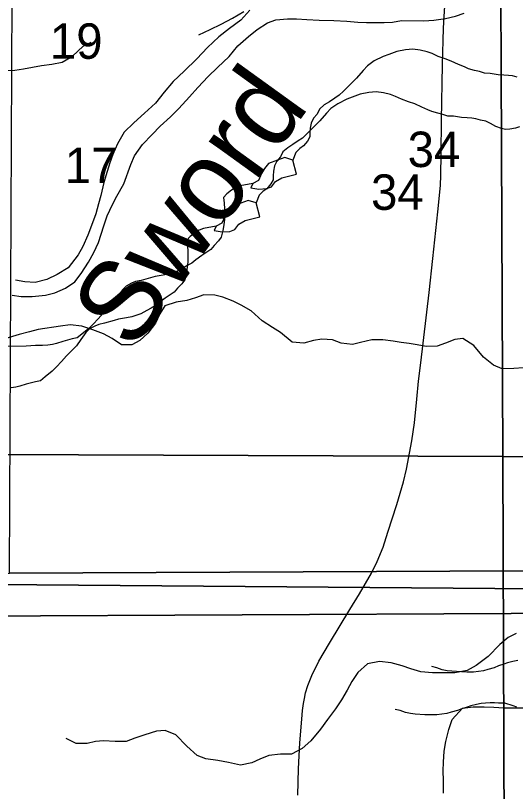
# Model space of a CAD drawing. Extents: x -21.1 to 50.3, y -4.9 to 22.1.
# Drawn here: x 5.889 to 6.48, y 18.75 to 19.666 of the extents above; entities that cross this region are included whole.
import ezdxf

# ---------------------------------------------------------------- set-up
doc = ezdxf.new("R2010")
doc.units = 0
for name, color, linetype in [('GM_X_Minor_Lake', 7, 'Continuous'), ('GM_X_Minor_River', 7, 'Continuous'), ('GM_X_Minor_River_Text', 7, 'Continuous'), ('GM_X_Section', 7, 'Continuous'), ('GM_X_Section_Text', 7, 'Continuous'), ('GM_X_State_Route', 7, 'Continuous')]:
    doc.layers.add(name, color=color, linetype=linetype)

msp = doc.modelspace()

# ---------------------------------------------------------------- linework, layer by layer
at = {"layer": 'GM_X_Minor_Lake'}
for points in [[(6.21674, 19.49534), (6.20723, 19.49828), (6.19854, 19.49515), (6.18797, 19.49124), (6.1831, 19.4855), (6.17975, 19.47939), (6.17605, 19.47138), (6.16926, 19.46789), (6.16705, 19.46256), (6.17654, 19.46114), (6.18564, 19.46162), (6.1913, 19.46395), (6.19617, 19.47008), (6.2037, 19.47433), (6.21165, 19.47632), (6.2211, 19.47869)], [(6.2211, 19.47869), (6.21674, 19.49534)], [(6.17345, 19.44483), (6.16394, 19.44776), (6.15525, 19.44463), (6.14468, 19.44072), (6.13981, 19.43498), (6.13646, 19.42887), (6.13276, 19.42086), (6.12598, 19.41738), (6.12376, 19.41204), (6.13326, 19.41062), (6.14235, 19.4111), (6.14802, 19.41344), (6.15288, 19.41956), (6.16042, 19.42382), (6.16836, 19.4258), (6.17781, 19.42818)], [(6.17781, 19.42818), (6.17345, 19.44483)]]:
    msp.add_lwpolyline(points, dxfattribs=at)
at = {"layer": 'GM_X_Minor_River'}
for points in [[(5.8849, 19.33589), (5.89589, 19.33426), (5.9088, 19.33413), (5.92438, 19.33587), (5.93541, 19.33841), (5.948, 19.34398), (5.95909, 19.35147), (5.9664, 19.36127), (5.97527, 19.37486), (5.98146, 19.38619), (5.9869, 19.39791), (5.99003, 19.40776), (5.99355, 19.4176), (5.99747, 19.42933), (6.00368, 19.44294), (6.00872, 19.45277), (6.01684, 19.4675), (6.02543, 19.49021), (6.02971, 19.50042), (6.03895, 19.51362), (6.05047, 19.52566), (6.06006, 19.53544), (6.07232, 19.54633), (6.08191, 19.55649), (6.09458, 19.57004), (6.10456, 19.58095), (6.11647, 19.59412), (6.12758, 19.60465), (6.14138, 19.6178), (6.15176, 19.63023), (6.16441, 19.6415), (6.17436, 19.64976), (6.18659, 19.65761), (6.19649, 19.66093), (6.21055, 19.66231), (6.22118, 19.6622), (6.23332, 19.66132), (6.24774, 19.66079), (6.2652, 19.66023), (6.28037, 19.65932), (6.29365, 19.65843), (6.30389, 19.65794), (6.32477, 19.65773), (6.33427, 19.65839), (6.34491, 19.66018), (6.37148, 19.65991), (6.38326, 19.66056), (6.39695, 19.6627), (6.40874, 19.66524), (6.41903, 19.66893)], [(6.16586, 19.67226), (6.15511, 19.66059), (6.14173, 19.65085), (6.1291, 19.6411), (6.11568, 19.62832), (6.1034, 19.61515), (6.08844, 19.60049), (6.07541, 19.58808), (6.06465, 19.57566), (6.05426, 19.56247), (6.04124, 19.55082), (6.02897, 19.53955), (6.01747, 19.52827), (6.00936, 19.51468), (6.00391, 19.50182), (6.00039, 19.49198), (5.99725, 19.48176), (5.99332, 19.46888), (5.98975, 19.45372), (5.98699, 19.44387), (5.98383, 19.43175), (5.97992, 19.42115), (5.97446, 19.40677), (5.96863, 19.39316), (5.96321, 19.38334), (5.95129, 19.36826), (5.9383, 19.36004), (5.92609, 19.35446), (5.91239, 19.3508), (5.89987, 19.35169), (5.88888, 19.3537)], [(6.10577, 19.64349), (6.11904, 19.64956), (6.13193, 19.65601), (6.1452, 19.66284), (6.15886, 19.67081)], [(5.72814, 19.54864), (5.74103, 19.5494), (5.7543, 19.55129), (5.7691, 19.56381), (5.78161, 19.57595), (5.7945, 19.58467), (5.80777, 19.58505), (5.81952, 19.58051), (5.83128, 19.58126), (5.84265, 19.59226), (5.85593, 19.59833), (5.86616, 19.59947), (5.87867, 19.60099), (5.88815, 19.60175), (5.89839, 19.60327), (5.909, 19.60517), (5.91962, 19.60706), (5.93175, 19.60858), (5.94426, 19.61086), (5.9564, 19.61807), (5.96891, 19.62983), (5.97839, 19.63476)], [(6.4817, 19.59322), (6.47636, 19.59471), (6.47141, 19.59544), (6.46608, 19.59579), (6.45922, 19.59613), (6.4497, 19.5976), (6.44322, 19.59795), (6.43712, 19.59981), (6.4314, 19.6013), (6.42416, 19.60316), (6.41958, 19.60541), (6.41233, 19.60841), (6.40394, 19.61216), (6.39669, 19.61478), (6.3883, 19.61778), (6.38143, 19.62116), (6.37533, 19.6234), (6.36694, 19.62526), (6.35856, 19.62635), (6.34981, 19.62554), (6.33954, 19.62358), (6.33004, 19.62011), (6.32359, 19.6178), (6.31296, 19.61242), (6.305, 19.60668), (6.2997, 19.60133), (6.29176, 19.59217), (6.27661, 19.57689), (6.27131, 19.57192), (6.26638, 19.56847), (6.25994, 19.56426), (6.25387, 19.56043), (6.24818, 19.55546), (6.24555, 19.54975), (6.24101, 19.54478), (6.23838, 19.53907), (6.23727, 19.53298), (6.23692, 19.52728), (6.23657, 19.52272), (6.23393, 19.51777), (6.2294, 19.51205), (6.22484, 19.50898), (6.22037, 19.50433), (6.21671, 19.49535)], [(6.48451, 19.5346), (6.47957, 19.53305), (6.47311, 19.53188), (6.46778, 19.53147), (6.46321, 19.53258), (6.45634, 19.53521), (6.45023, 19.53859), (6.44451, 19.54122), (6.43841, 19.5427), (6.43307, 19.54419), (6.42812, 19.54493), (6.42279, 19.54528), (6.41593, 19.54562), (6.40641, 19.54708), (6.39994, 19.54743), (6.39383, 19.5493), (6.38812, 19.55078), (6.38087, 19.55264), (6.37629, 19.5549), (6.36904, 19.5579), (6.36065, 19.56165), (6.3534, 19.56427), (6.34501, 19.56726), (6.33814, 19.57064), (6.33204, 19.57289), (6.32365, 19.57474), (6.31527, 19.57583), (6.30652, 19.57502), (6.29625, 19.57307), (6.28676, 19.5696), (6.2803, 19.56728), (6.26967, 19.5619), (6.26171, 19.55616), (6.25641, 19.55081), (6.24847, 19.54165), (6.23332, 19.52637), (6.22802, 19.5214), (6.2231, 19.51796), (6.21665, 19.51375), (6.21058, 19.50991), (6.20489, 19.50494), (6.20226, 19.49923), (6.19772, 19.49427), (6.19509, 19.48855), (6.19398, 19.48247), (6.19363, 19.47677), (6.19328, 19.47221), (6.19064, 19.46725), (6.18611, 19.46153), (6.18155, 19.45847), (6.17708, 19.45381), (6.17342, 19.44484)], [(6.16926, 19.46789), (6.15453, 19.46495), (6.14935, 19.46298), (6.14404, 19.45991), (6.13873, 19.4557), (6.13457, 19.45112), (6.13537, 19.44467), (6.13579, 19.43783), (6.13586, 19.42568), (6.13513, 19.41883), (6.13403, 19.41237), (6.13217, 19.40438), (6.12877, 19.3998), (6.12385, 19.39446), (6.11969, 19.38988), (6.10907, 19.3826), (6.10225, 19.37762), (6.09732, 19.3738)], [(6.12598, 19.41738), (6.11124, 19.41444), (6.10606, 19.41246), (6.10075, 19.4094), (6.09544, 19.40519), (6.09128, 19.4006), (6.09208, 19.39415), (6.0925, 19.38731), (6.09257, 19.37516), (6.09185, 19.36832), (6.09074, 19.36185), (6.08888, 19.35386), (6.08548, 19.34929), (6.08056, 19.34394), (6.0764, 19.33936), (6.06578, 19.33208), (6.05896, 19.32711), (6.05403, 19.32328)], [(6.09732, 19.3738), (6.09277, 19.37111), (6.08745, 19.36804), (6.08024, 19.3642), (6.07568, 19.36266), (6.0696, 19.36073), (6.06352, 19.35955), (6.05401, 19.35798), (6.04869, 19.35643), (6.03729, 19.35333), (6.03083, 19.35178), (6.02589, 19.34985), (6.01982, 19.3464), (6.01527, 19.34219), (6.00961, 19.3338), (6.00432, 19.32655), (5.99903, 19.32083), (5.99259, 19.31471), (5.98654, 19.30784), (5.98086, 19.30173), (5.97556, 19.29638), (5.96722, 19.28988), (5.96192, 19.28529), (5.95584, 19.28412), (5.94482, 19.28102), (5.9376, 19.2787), (5.93265, 19.27753), (5.92733, 19.27675), (5.92086, 19.27633), (5.91249, 19.27628), (5.90716, 19.27587), (5.90145, 19.27546), (5.87823, 19.27534)], [(6.20225, 19.29154), (6.19278, 19.29761), (6.18027, 19.30557), (6.16739, 19.31733), (6.15564, 19.32415), (6.14617, 19.32871), (6.13404, 19.33326), (6.12456, 19.33591), (6.11168, 19.33629), (6.10182, 19.33249), (6.09158, 19.32946), (6.07869, 19.32756), (6.06542, 19.32339), (6.05973, 19.3139), (6.05442, 19.3029), (6.04531, 19.29077), (6.03583, 19.28242), (6.02635, 19.27711), (6.01422, 19.27711), (6.00323, 19.28469), (5.993, 19.29), (5.98049, 19.29493), (5.96722, 19.2991), (5.95358, 19.30062), (5.9422, 19.2991), (5.91566, 19.2953), (5.90543, 19.29265), (5.89329, 19.28923), (5.87775, 19.28468)], [(6.05403, 19.32328), (6.04948, 19.3206), (6.04417, 19.31753), (6.03695, 19.31369), (6.03239, 19.31215), (6.02631, 19.31021), (6.02023, 19.30904), (6.01072, 19.30747), (6.0054, 19.30592), (5.994, 19.30282), (5.98754, 19.30126), (5.9826, 19.29933), (5.97653, 19.29588), (5.97199, 19.29168), (5.96632, 19.28329), (5.96103, 19.27604), (5.95574, 19.27031), (5.9493, 19.2642), (5.94325, 19.25733), (5.93757, 19.25122), (5.93227, 19.24587), (5.92394, 19.23937), (5.91863, 19.23478), (5.91255, 19.23361), (5.90153, 19.2305), (5.89431, 19.22818), (5.88936, 19.22702), (5.88404, 19.22623)], [(6.48919, 19.24986), (6.47782, 19.2491), (6.46417, 19.24872), (6.45394, 19.25326), (6.44182, 19.26274), (6.43045, 19.2764), (6.41757, 19.28474), (6.40809, 19.2836), (6.39709, 19.27905), (6.38724, 19.27564), (6.37435, 19.27525), (6.36373, 19.27715), (6.35426, 19.27867), (6.34478, 19.2798), (6.3353, 19.28132), (6.32318, 19.28321), (6.30991, 19.28321), (6.29664, 19.2798), (6.28716, 19.27752), (6.27389, 19.27904), (6.26366, 19.28321), (6.25077, 19.28396), (6.24092, 19.28207), (6.22954, 19.27903), (6.2159, 19.28017), (6.20225, 19.29154)], [(6.48069, 18.9362), (6.47121, 18.93164), (6.46135, 18.9233), (6.44732, 18.90889), (6.43328, 18.89826), (6.42267, 18.89257), (6.40826, 18.88954), (6.39651, 18.88954), (6.38172, 18.88991), (6.36808, 18.89105), (6.35595, 18.89446), (6.34572, 18.89787), (6.33283, 18.90167), (6.31918, 18.90318), (6.30478, 18.90052), (6.2934, 18.89028), (6.28657, 18.87966), (6.28088, 18.86942), (6.27405, 18.85766), (6.26722, 18.84704), (6.25774, 18.83453), (6.24939, 18.82315), (6.23801, 18.80949), (6.22777, 18.80039), (6.21526, 18.79356), (6.20199, 18.79356), (6.18835, 18.79204), (6.17773, 18.78787), (6.16825, 18.78332), (6.15498, 18.78066), (6.14058, 18.78369), (6.12807, 18.78635), (6.11404, 18.78824), (6.10381, 18.79203), (6.0913, 18.80303), (6.07842, 18.8163), (6.06592, 18.82161), (6.05568, 18.82085), (6.04165, 18.81668), (6.0299, 18.81251), (6.01966, 18.80871), (6.00677, 18.80871), (5.99312, 18.80947), (5.98365, 18.80871), (5.97379, 18.80643), (5.96052, 18.80643), (5.94877, 18.81212)], [(6.4825, 18.90411), (6.4768, 18.90294), (6.47034, 18.90138), (6.46578, 18.89984), (6.4597, 18.8979), (6.45438, 18.8956), (6.44716, 18.89366), (6.44184, 18.89211), (6.43613, 18.89132), (6.43005, 18.89052), (6.42243, 18.89048), (6.41596, 18.89083), (6.40454, 18.89152), (6.39883, 18.89225), (6.39311, 18.89336), (6.38663, 18.8956), (6.38091, 18.89709)], [(6.48149, 18.84927), (6.47692, 18.85076), (6.467, 18.85375), (6.45977, 18.85371), (6.45481, 18.85444), (6.44987, 18.85441), (6.44416, 18.854), (6.43921, 18.85359), (6.43351, 18.85242), (6.42705, 18.85087), (6.42249, 18.84932), (6.41641, 18.84739), (6.41109, 18.84508), (6.40387, 18.84314), (6.39855, 18.84159), (6.39285, 18.8408), (6.38676, 18.84001), (6.37915, 18.83997), (6.37267, 18.84031), (6.36125, 18.84101), (6.35554, 18.84173), (6.34982, 18.84284), (6.34334, 18.84509), (6.33762, 18.84657)], [(6.39473, 18.74763), (6.3945, 18.76245), (6.39424, 18.77385), (6.39473, 18.7841), (6.39562, 18.79738), (6.39726, 18.80876), (6.40082, 18.82278), (6.40512, 18.83451), (6.41702, 18.84807), (6.42956, 18.84946), (6.44285, 18.84971), (6.45424, 18.84921), (6.46599, 18.84833), (6.47586, 18.84823), (6.48953, 18.84847)]]:
    msp.add_lwpolyline(points, dxfattribs=at)
at = {"layer": 'GM_X_Section'}
for points in [[(5.46449, 20.1514), (6.46064, 20.14904), (6.46467, 19.14528), (5.46172, 19.1492)], [(6.46064, 20.14904), (7.44997, 20.14748), (7.45853, 19.14217), (6.46467, 19.14528)], [(5.88662, 20.02845), (6.88082, 20.03211), (6.88772, 19.01332), (6.83581, 19.01172), (5.8818, 19.00728)], [(5.45185, 20.01395), (6.49363, 20.00748), (6.50457, 18.98884), (5.47114, 18.99721)], [(5.84333, 19.97793), (6.83753, 19.9816), (6.84443, 18.96281), (6.79252, 18.9612), (5.83851, 18.95676)], [(5.46172, 19.1492), (6.46467, 19.14528), (6.46827, 18.13471), (5.45742, 18.14589)], [(6.46467, 19.14528), (7.45853, 19.14217), (7.46215, 18.13462), (6.46827, 18.13471)], [(6.83581, 19.01172), (6.83569, 18.01448), (5.81893, 17.99203), (5.82494, 19.00715), (5.8818, 19.00728)], [(6.50457, 18.98884), (6.51666, 17.95921), (5.48815, 17.97251), (5.47114, 18.99721)], [(6.79252, 18.9612), (6.7924, 17.96396), (5.77564, 17.94152), (5.78166, 18.95663), (5.83851, 18.95676)]]:
    msp.add_lwpolyline(points, close=True, dxfattribs=at)
at = {"layer": 'GM_X_State_Route'}
msp.add_lwpolyline([(6.22252, 18.74512), (6.22333, 18.77626), (6.22499, 18.80723), (6.22716, 18.83516), (6.22824, 18.84505), (6.22934, 18.85356), (6.23029, 18.85947), (6.23165, 18.86603), (6.23456, 18.87495), (6.23927, 18.88662), (6.24749, 18.90339), (6.25987, 18.92493), (6.28413, 18.96465), (6.29558, 18.98309), (6.30949, 19.00728), (6.31637, 19.02109), (6.32327, 19.03831), (6.32899, 19.05585), (6.33942, 19.08851), (6.34745, 19.11523), (6.35109, 19.13026), (6.35738, 19.16364), (6.36023, 19.18518), (6.36299, 19.21279), (6.36531, 19.23442), (6.36783, 19.256), (6.37786, 19.33898), (6.38203, 19.37896), (6.38815, 19.43439), (6.39099, 19.46515), (6.39164, 19.4775), (6.39213, 19.50225), (6.39248, 19.54255), (6.3935, 19.60775), (6.3947, 19.65118), (6.39693, 19.69148)], dxfattribs=at)

# ---------------------------------------------------------------- texts
at = {"layer": 'GM_X_Minor_River_Text'}
msp.add_text('Sword', height=0.094729, rotation=54.20577, dxfattribs=at).set_placement((6.0272, 19.26795))
at = {"layer": 'GM_X_Section_Text'}
for s, p in [('19', (5.92961, 19.61498)), ('34', (6.35234, 19.48713)), ('17', (5.9472, 19.46817)), ('34', (6.30906, 19.43661))]:
    msp.add_text(s, height=0.041856, rotation=0.00001, dxfattribs=at).set_placement(p)

doc.saveas('drawing.dxf')
